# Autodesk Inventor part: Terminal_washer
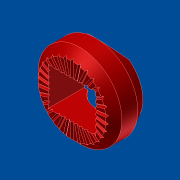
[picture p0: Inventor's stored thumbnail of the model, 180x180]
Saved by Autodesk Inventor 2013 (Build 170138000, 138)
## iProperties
Shininess: 20.0
Length Units: 11269
Angle Units: 11279
Time Units: 11290
Mass Units: 11283
Length Display Precision: 3
Angle Display Precision: 2
Created: 2001-04
Part Number: Terminal_washer
Material: Standard
Document SubType Name: Modellieren
Designer: dl
Density: 1 g/cm^3
Density: 0.0
Volumn: 0.0
Area: 0.0
PropertySet Name: Model Information
Control State: 0
Master: False
Checked Out: False
Author: dl
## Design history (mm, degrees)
body "Solid1"
sketch "Sketch1"
  geometry: C1 r 10.5 at (11.476, 10.276)
  constraints: 1 centre point
  dimensions: "d0" = 21 diameter of C1
extrude "Extrusion1" new body sketch "Sketch1" distance "d1" = 9; taper "d2" = 0 deg
sketch "Sketch2"
  geometry: L1 (6, 4.75)-(-6, 4.75); L2 (-6, -4.75)-(6, -4.75); L3 (-6, 4.75)-(-6, -4.75); L4 (6, -4.75)-(6, 4.75)
  constraints: 8 end point
extrude "Extrusion2" cut sketch "Sketch2" stored distance "d3" = 9; taper "d4" = 0 deg
sketch "Sketch4"
  geometry: L1 (0, 8.65)-(-0.35, 9); L2 (-0.35, 9)-(0.35, 9); L3 (0.35, 9)-(0, 8.65); L4 (-8.5, 9)-(8.5, 9) reference; L5 (0, 9)-(0, 7); L6 (10.5, 7)-(-10.5, 7) reference
  constraints: 8 end point, 2 perpendicular, 1 horizontal, 1 midpoint
  dimensions: "d21" = 45 deg angle of L1 L2; "d22" = 0.7 distance of L1.end L2.end; "d23" = 0 distance between parallel lines of L4 L2; "d24" = 0 horizontal distance of L1.start L5.start
extrude "Extrusion4" cut sketch "Sketch4" stored distance "d25" = 9; taper "d26" = 0 deg
chamfer "Chamfer1" distance "d5" = 2; stored, may be unused: second distance "d6" = 2, angle "d30" = 45 deg
chamfer "Chamfer2" distance "d7" = 3; stored, may be unused: angle "d8" = 30 deg, second distance "d31" = 3
sketch "Sketch3"
  geometry: L1 (-19.976, 9)-(-2.976, 9) reference; L2 (-11.65, 9.433)-(-11.65, 12.476); C1 r 6 at (-11.65, -3)
  constraints: 2 end point, 1 centre point, 1 perpendicular
  dimensions: "d14" = 12 diameter of C1; "d15" = 12 distance from line of L1 C1.centre; "d16" = 0 horizontal distance of L2.end C1.centre
extrude "Extrusion3" cut sketch "Sketch3" stored distance "d17" = 9; taper "d18" = 0 deg
workaxis "Work Axis1"
workplane "Work Plane1"
pattern_circular "Circular Pattern1" dims angle "d29" = 360 deg
other parameters: "d19" = 0, "d20" = 0
